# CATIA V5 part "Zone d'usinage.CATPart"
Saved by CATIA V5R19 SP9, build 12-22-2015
Part number: Zone d'usinage
Bounding box of the stored display mesh (mm): x 0 to 263, y 0 to 295, z -84 to 0
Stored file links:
  Z:\fausse table rondelle-20220905T211342Z-001\fausse table rondelle\Zone d'usinage.CATPart
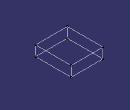
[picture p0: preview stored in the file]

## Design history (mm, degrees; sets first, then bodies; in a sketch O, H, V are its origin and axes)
AxisSystem1: origin (0, 0, 0), X (1, 0, 0), Y (0, 1, 0), Z (0, 0, 1)
Body1 (main body)
  Sketch1 on XY plane of AxisSystem1, origin (0, 0, 0), H (1, 0, 0), V (0, 1, 0)
    line L1 (0, 0) -> (263, 0)
    line L2 (263, 0) -> (263, 295)
    line L3 (263, 295) -> (0, 295)
    line L4 (0, 295) -> (0, 0)
    length L2 = 295
    length L3 = 263
    horizontal: L1 H, L3 H
    vertical: L2 V, L4 V
  Pad1: profile Sketch1, direction (0, 0, -1), length 84
  Line1: type PtPt, FirstPoint vertex [face of Pad1 from Sketch1.L2 | start face of Pad1 | face of Pad1 from Sketch1.L1], SecondPoint vertex [face of Pad1 from Sketch1.L1 | face of Pad1 from Sketch1.L2 | end face of Pad1]
  Line2: type PtPt, FirstPoint vertex of Line1, SecondPoint vertex [face of Pad1 from Sketch1.L2 | end face of Pad1 | face of Pad1 from Sketch1.L3]
  Line3: type PtPt, FirstPoint vertex [face of Pad1 from Sketch1.L2 | face of Pad1 from Sketch1.L3 | start face of Pad1], SecondPoint vertex of Line2
  Line4: type PtPt, FirstPoint vertex of Line1, SecondPoint vertex of Line3
  Line5: type PtPt, FirstPoint vertex of Line3, SecondPoint vertex [face of Pad1 from Sketch1.L3 | start face of Pad1 | face of Pad1 from Sketch1.L4]
  Line6: type PtPt, FirstPoint vertex of Line2, SecondPoint vertex [face of Pad1 from Sketch1.L3 | face of Pad1 from Sketch1.L4 | end face of Pad1]
  Line7: type PtPt, FirstPoint vertex of Line5, SecondPoint vertex of Line6
  Line8: type PtPt, FirstPoint vertex of Line1, SecondPoint vertex [YZ plane of AxisSystem1 | ZX plane of AxisSystem1 | XY plane of AxisSystem1]
  Line9: type PtPt, FirstPoint vertex of Line1, SecondPoint vertex [face of Pad1 from Sketch1.L4 | end face of Pad1 | face of Pad1 from Sketch1.L1]
  Line10: type PtPt, FirstPoint vertex of Line9, SecondPoint vertex of Line8
  Line11: type PtPt, FirstPoint vertex of Line8, SecondPoint vertex of Line5
  Line12: type PtPt, FirstPoint vertex of Line6, SecondPoint vertex of Line9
